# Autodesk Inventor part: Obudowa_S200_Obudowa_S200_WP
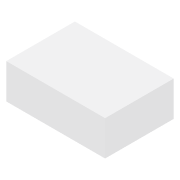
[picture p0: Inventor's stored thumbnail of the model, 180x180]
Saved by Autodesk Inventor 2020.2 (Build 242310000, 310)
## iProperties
Created: 2015-02
Part Number: Obudowa_S200_Obudowa_S200_WP
Material: Ogólny
Document SubType Name: Modeling
Designer: F.Stasiak
Density: 1 g/cm^3
Appearance: Domyślna
Catalog Web Link: www.expertbooks.pl
Manager: www.cadconsulting.pl
Company: Fabian Stasiak CAD Consulting
d0: -30.000 mm
d1: 85.000 mm
d2: 85.000 mm
d3: 59.000 mm
d4: 59.000 mm
d5: 60.000 mm
d6: 0.00 deg
Xmin: -85.000 mm
Ymin: -59.000 mm
Zmin: -30.000 mm
Xmax: 85.000 mm
Ymax: 59.000 mm
Zmax: 30.000 mm
Author: F.Stasiak
Subject: Zbiór ćwiczeń. Autodesk Inventor 2020. Kurs Professional
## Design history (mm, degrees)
sketch "Szkic1"
  geometry: L1 (-85, 59)-(85, 59); L2 (85, 59)-(85, -59); L3 (85, -59)-(-85, -59); L4 (-85, -59)-(-85, 59); 1 further point
  constraints: 8 end point, 2 parallel, 1 horizontal, 1 perpendicular, 1 other
  dimensions: "d1" = 85 distance from line of L4 point (0, 0) (= -Xmin); "d2" = 85 distance from line of L2 point (0, 0) (= Xmax); "d3" = 59 distance from line of L3 point (0, 0) (= -Ymin); "d4" = 59 distance from line of L1 point (0, 0) (= Ymax)
extrude "Wyciągnięcie proste1" join sketch "Szkic1" distance "d5" = 60 (= Zmax - Zmin); taper "d6" = 0 deg
node "Bryła1"
other parameters: "Xmin" = -85 [user parameter; used in 1 equation term], "Ymin" = -59 [user parameter; used in 1 equation term], "Zmin" = -30 [user parameter; used in 1 equation term], "Xmax" = 85 [user parameter; used in 1 equation term], "Ymax" = 59 [user parameter; used in 1 equation term], "Zmax" = 30 [user parameter; used in 1 equation term], "d0" = -30
